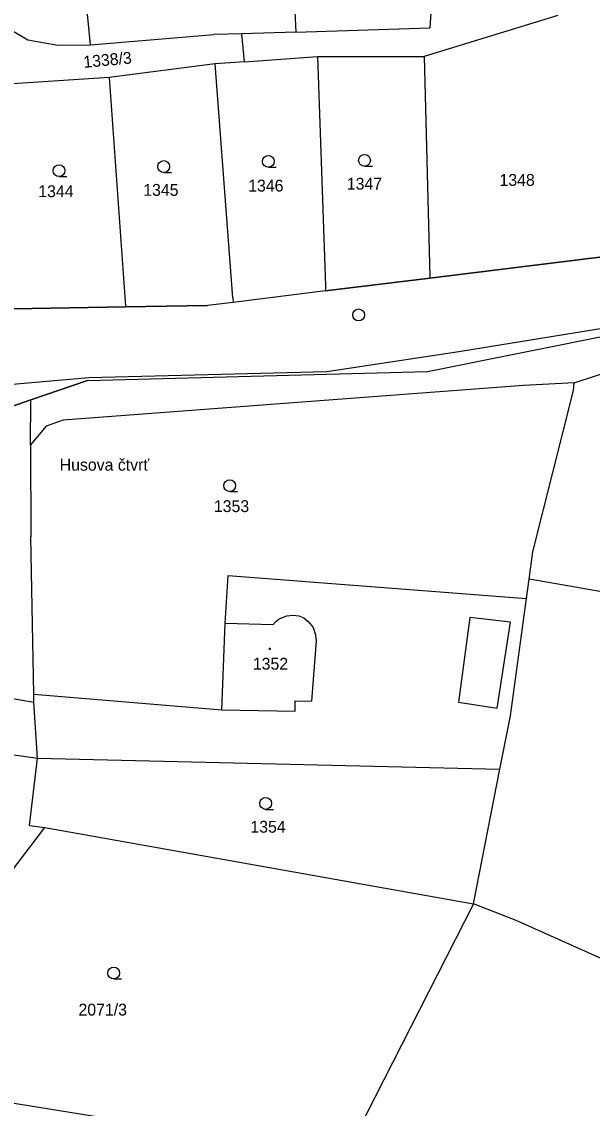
# Model space of a CAD drawing. Extents: x -805011 to -803920, y -1150790 to -1150234.
# Drawn here: x -804673 to -804600.8, y -1150606.5 to -1150469 of the extents above; entities that cross this region are included whole.
import ezdxf

# ---------------------------------------------------------------- set-up
doc = ezdxf.new("R2010")
doc.units = 0
for name, color, linetype in [('Default', 7, 'Continuous'), ('kilometráž - vrstava 7', 7, 'Continuous'), ('kn_celek - Cisla pozemkovych parcel', 7, 'Continuous'), ('kn_celek - Cisla stavebnich parcel', 7, 'Continuous'), ('kn_celek - Dalsi prvky mapy popis', 7, 'Continuous'), ('kn_celek - Hranice parcel', 7, 'Continuous'), ('kn_celek - Vnitrni kresby', 7, 'Continuous'), ('kn_celek - Znacky budov', 7, 'Continuous'), ('kn_celek - Znacky kultur', 7, 'Continuous'), ('plochy - SZDC', 7, 'Continuous'), ('PSR_C2_2_trasa_Vimperk - Kabelová trasa', 7, 'Continuous')]:
    doc.layers.add(name, color=color, linetype=linetype)

# ---------------------------------------------------------------- blocks, each defined once
blk = doc.blocks.new('304')
at = {"layer": 'Default'}
blk.add_line((-0.1, 0), (9.9, 0), dxfattribs=at)
blk.add_circle((-0.1, 7.5), 7.5, dxfattribs=at)
blk = doc.blocks.new('402')
at = {"layer": 'Default'}
for p, q in [((-0.8, 0.8), (0.7, 0.8)), ((-0.8, 0.8), (-0.8, -0.7)), ((0.7, 0.8), (0.7, -0.7)), ((0.7, -0.7), (-0.8, -0.7))]:
    blk.add_line(p, q, dxfattribs=at)

msp = doc.modelspace()

# ---------------------------------------------------------------- linework, layer by layer
at = {"layer": 'kilometráž - vrstava 7'}
msp.add_circle((-804630.34, -1150506.1), 0.75, dxfattribs=at)
at = {"layer": 'kn_celek - Hranice parcel'}
for p, q in [((-804638.87, -1150456.55), (-804638.3, -1150470.31)), ((-804620.84, -1150462.06), (-804621.34, -1150469.78)), ((-804664.29, -1150471.93), (-804664.84, -1150466.32)), ((-804605.13, -1150468.22), (-804622.06, -1150473.4)), ((-804675.65, -1150469.27), (-804672.2, -1150471.3)), ((-804638.3, -1150470.31), (-804621.34, -1150469.78)), ((-804664.29, -1150471.93), (-804648.66, -1150470.63)), ((-804645.14, -1150470.52), (-804648.66, -1150470.63)), ((-804638.3, -1150470.31), (-804645.14, -1150470.52)), ((-804644.8, -1150474.06), (-804645.14, -1150470.52)), ((-804672.2, -1150471.3), (-804668.41, -1150471.98)), ((-804668.41, -1150471.98), (-804664.29, -1150471.93)), ((-804644.8, -1150474.06), (-804635.53, -1150473.39)), ((-804635.53, -1150473.39), (-804622.06, -1150473.4)), ((-804635.53, -1150473.39), (-804634.55, -1150502.42)), ((-804622.06, -1150473.4), (-804621.33, -1150501.27)), ((-804648.48, -1150474.32), (-804661.91, -1150476.04)), ((-804644.8, -1150474.06), (-804648.48, -1150474.32)), ((-804646.26, -1150503.93), (-804648.48, -1150474.32)), ((-804661.91, -1150476.04), (-804676.51, -1150477.02)), ((-804661.91, -1150476.04), (-804659.85, -1150504.98)), ((-804621.33, -1150501.45), (-804598.8, -1150498.68)), ((-804621.33, -1150501.27), (-804621.33, -1150501.45)), ((-804634.55, -1150502.42), (-804634.52, -1150503.07)), ((-804634.52, -1150503.07), (-804621.33, -1150501.45)), ((-804646.26, -1150503.93), (-804646.22, -1150504.51)), ((-804634.52, -1150503.07), (-804646.22, -1150504.51)), ((-804621.63, -1150513.27), (-804572.18, -1150503.29)), ((-804674.03, -1150505.33), (-804659.84, -1150505.09)), ((-804659.85, -1150504.98), (-804659.84, -1150505.09)), ((-804659.84, -1150505.09), (-804649.49, -1150504.92)), ((-804646.22, -1150504.51), (-804649.49, -1150504.92)), ((-804603.08, -1150514.69), (-804588.25, -1150509.82)), ((-804664.68, -1150514.39), (-804621.63, -1150513.27)), ((-804664.68, -1150514.39), (-804671.85, -1150516.86)), ((-804609.46, -1150515.04), (-804667.73, -1150519.42)), ((-804603.08, -1150514.69), (-804609.46, -1150515.04)), ((-804603.16, -1150515.68), (-804603.08, -1150514.69)), ((-804608.29, -1150536.06), (-804603.16, -1150515.68)), ((-804671.85, -1150516.86), (-804677.85, -1150518.93)), ((-804671.87, -1150522.56), (-804671.85, -1150516.86)), ((-804669.9, -1150520.19), (-804671.87, -1150522.56)), ((-804667.73, -1150519.42), (-804669.9, -1150520.19)), ((-804671.87, -1150522.56), (-804671.82, -1150534.17)), ((-804671.45, -1150554.09), (-804671.82, -1150534.17)), ((-804608.76, -1150539.53), (-804608.29, -1150536.06)), ((-804647.25, -1150545.14), (-804646.84, -1150539.07)), ((-804646.84, -1150539.07), (-804609.1, -1150542)), ((-804609.1, -1150542), (-804608.76, -1150539.53)), ((-804603.64, -1150540.42), (-804608.76, -1150539.53)), ((-804558.89, -1150548.22), (-804603.64, -1150540.42)), ((-804611.13, -1150556.84), (-804609.1, -1150542)), ((-804647.67, -1150556.08), (-804647.25, -1150545.14)), ((-804679.04, -1150553.78), (-804671.44, -1150555.09)), ((-804671.44, -1150555.09), (-804671.45, -1150554.09)), ((-804671.45, -1150554.09), (-804647.67, -1150556.08)), ((-804670.97, -1150562.21), (-804671.44, -1150555.09)), ((-804612.45, -1150563.56), (-804611.13, -1150556.84)), ((-804676.7, -1150561.39), (-804670.97, -1150562.21)), ((-804672.02, -1150570.73), (-804670.97, -1150562.21)), ((-804670.97, -1150562.21), (-804612.45, -1150563.56)), ((-804615.82, -1150580.63), (-804612.45, -1150563.56)), ((-804677.01, -1150580.07), (-804670.08, -1150570.98)), ((-804672.02, -1150570.73), (-804670.08, -1150570.98)), ((-804670.08, -1150570.98), (-804615.82, -1150580.63)), ((-804615.82, -1150580.63), (-804632.2, -1150612.75)), ((-804610.41, -1150582.75), (-804615.82, -1150580.63)), ((-804575.08, -1150598.55), (-804610.41, -1150582.75)), ((-804653.81, -1150609.12), (-804694.22, -1150602.66))]:
    msp.add_line(p, q, dxfattribs=at)
at = {"layer": 'kn_celek - Vnitrni kresby'}
for p, q in [((-804641.21, -1150545.33), (-804647.25, -1150545.14)), ((-804641.21, -1150545.33), (-804640.81, -1150544.9)), ((-804640.81, -1150544.9), (-804640.38, -1150544.56)), ((-804640.38, -1150544.56), (-804639.43, -1150544.16)), ((-804639.43, -1150544.16), (-804638.64, -1150544.08)), ((-804638.64, -1150544.08), (-804637.92, -1150544.19)), ((-804637.92, -1150544.19), (-804637.29, -1150544.45)), ((-804637.29, -1150544.45), (-804636.73, -1150544.88)), ((-804636.73, -1150544.88), (-804636.11, -1150545.64)), ((-804616.26, -1150544.39), (-804617.7, -1150555.12)), ((-804611.13, -1150545), (-804616.26, -1150544.39)), ((-804612.8, -1150555.87), (-804611.13, -1150545)), ((-804636.11, -1150545.64), (-804635.79, -1150546.57)), ((-804635.79, -1150546.57), (-804635.73, -1150547.34)), ((-804635.73, -1150547.34), (-804636.29, -1150554.98)), ((-804638.39, -1150556.25), (-804638.37, -1150554.94)), ((-804638.37, -1150554.94), (-804636.29, -1150554.98)), ((-804647.67, -1150556.08), (-804638.39, -1150556.25)), ((-804617.7, -1150555.12), (-804612.8, -1150555.87))]:
    msp.add_line(p, q, dxfattribs=at)
at = {"layer": 'plochy - SZDC'}
for p, q in [((-804598.8, -1150498.68), (-804621.33, -1150501.45)), ((-804621.33, -1150501.45), (-804634.52, -1150503.07)), ((-804634.52, -1150503.07), (-804646.22, -1150504.51)), ((-804621.63, -1150513.27), (-804572.18, -1150503.29)), ((-804659.84, -1150505.09), (-804674.03, -1150505.33)), ((-804649.49, -1150504.92), (-804659.84, -1150505.09)), ((-804646.22, -1150504.51), (-804649.49, -1150504.92)), ((-804664.68, -1150514.39), (-804621.63, -1150513.27)), ((-804671.85, -1150516.86), (-804664.68, -1150514.39)), ((-804677.85, -1150518.93), (-804671.85, -1150516.86))]:
    msp.add_line(p, q, dxfattribs=at)
at = {"layer": 'PSR_C2_2_trasa_Vimperk - Kabelová trasa'}
for p, q in [((-804617.64, -1150510.74), (-804590.41, -1150506.27)), ((-804634.35, -1150513.26), (-804617.64, -1150510.74)), ((-804664.5, -1150514.01), (-804634.35, -1150513.26)), ((-804688.16, -1150516.11), (-804664.5, -1150514.01))]:
    msp.add_line(p, q, dxfattribs=at)

# ---------------------------------------------------------------- block references
at = {"layer": 'kn_celek - Znacky budov', "xscale": 0.1, "yscale": 0.10000000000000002}
msp.add_blockref('402', (-804641.6, -1150548.35), dxfattribs=at)
at = {"layer": 'kn_celek - Znacky kultur', "xscale": 0.1, "yscale": 0.10000000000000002}
for p in [(-804641.76, -1150487.42), (-804629.59, -1150487.29), (-804668.25, -1150488.6), (-804655, -1150488.08), (-804646.65, -1150528.46), (-804642.1, -1150568.67), (-804661.33, -1150590.13)]:
    msp.add_blockref('304', p, dxfattribs=at)

# ---------------------------------------------------------------- texts
at = {"layer": 'kn_celek - Cisla pozemkovych parcel'}
msp.add_text('1338/3', height=1.5, rotation=5.4, dxfattribs=at).set_placement((-804665.11, -1150474.85))
for s, p in [('1346', (-804644.32, -1150490.49)), ('1347', (-804631.84, -1150490.25)), ('1348', (-804612.51, -1150489.77)), ('1344', (-804670.89, -1150491.2)), ('1345', (-804657.6, -1150491.03)), ('1353', (-804648.66, -1150531.05)), ('1354', (-804644.04, -1150571.62)), ('2071/3', (-804665.8, -1150594.76))]:
    msp.add_text(s, height=1.5, dxfattribs=at).set_placement(p)
at = {"layer": 'kn_celek - Cisla stavebnich parcel'}
msp.add_text('1352', height=1.5, dxfattribs=at).set_placement((-804643.73, -1150550.99))
at = {"layer": 'kn_celek - Dalsi prvky mapy popis'}
msp.add_text('Husova čtvrť', height=1.5, dxfattribs=at).set_placement((-804668.18, -1150525.81))

doc.saveas('drawing.dxf')
